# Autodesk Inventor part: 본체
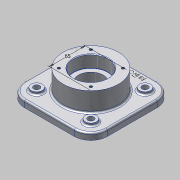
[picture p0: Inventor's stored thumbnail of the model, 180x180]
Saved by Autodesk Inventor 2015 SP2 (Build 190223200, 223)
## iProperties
Created: 2015-07
Part Number: 본체
Material: 알루미늄 6061
Document SubType Name: Modeling
Designer: AMC
Density: 2.7 g/cm^3
Appearance: 알루미늄 - 평지
Author: AMC
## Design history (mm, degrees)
sketch "스케치1"
  geometry: L1 (75, -75)-(-75, -75); L2 (-75, -75)-(-75, 75); L3 (-75, 75)-(75, 75); L4 (75, 75)-(75, -75); L5 (75, -75)-(-75, 75); L6 (-75, -75)-(75, 75); 1 further point
  constraints: 12 end point, 2 midpoint, 2 parallel, 1 horizontal, 1 perpendicular
  dimensions: "d0" = 150 distance of L2.end L3.end; "d1" = 150 distance of L1.end L2.end
extrude "돌출1" new body sketch "스케치1" distance "d2" = 12; taper "d3" = 0 deg
sketch "스케치2"
  geometry: C1 r 50 at (0, 0); 1 further point
  constraints: 1 centre point, 1 coincident
  dimensions: "d4" = 100 diameter of C1
extrude "돌출2" join sketch "스케치2" distance "d5" = 35; taper "d6" = 0 deg
sketch "스케치3"
  geometry: C1 r 50 at (0, 0); 1 further point
  constraints: 1 centre point, 1 coincident
  dimensions: "d7" = 100 diameter of C1
extrude "돌출3" join sketch "스케치3" distance "d8" = 23; taper "d9" = 0 deg
hole "구멍1" diameter "d12" = 45; stored, may be unused: countersink angle "d16" = 90 deg, drill point angle "d18" = 0 deg; dims "d10" = 10, "d11" = 10, "d13" = 6, "d14" = 62, "d15" = 22, "d17" = 8
hole "구멍2" diameter "d21" = 45; stored, may be unused: countersink angle "d25" = 90 deg, drill point angle "d27" = 0 deg; dims "d19" = 10, "d20" = 10, "d22" = 6, "d23" = 62, "d24" = 22, "d26" = 8
fillet "모깎기3" dims "d33" = 30
sketch "스케치8"
  geometry: C1 r 10 at (-49, 49); C2 r 10 at (-49, -49); C3 r 10 at (49, -49); C4 r 10 at (49, 49); 1 further point
  constraints: 4 centre point, 1 horizontal alignment, 9 other
  dimensions: "d34" = 20 diameter of C1; "d37" = 360 deg dimension on point (0, 0) C1.centre (derived); "d39" = 98 distance of C4.centre C1.centre; "d40" = 98 distance of C2.centre C1.centre (derived)
extrude "돌출4" join sketch "스케치8" distance "d41" = 5; taper "d42" = 0 deg
hole "구멍3" diameter "d45" = 11; stored, may be unused: countersink angle "d49" = 90 deg, drill point angle "d51" = 0 deg; dims "d43" = 10, "d44" = 10, "d46" = 6, "d47" = 62, "d48" = 22, "d50" = 8
hole "구멍4" diameter "d54" = 11; stored, may be unused: countersink angle "d58" = 90 deg, drill point angle "d60" = 0 deg; dims "d52" = 10, "d53" = 10, "d55" = 6, "d56" = 62, "d57" = 22, "d59" = 8
hole "구멍5" diameter "d63" = 11; stored, may be unused: countersink angle "d67" = 90 deg, drill point angle "d69" = 0 deg; dims "d61" = 10, "d62" = 10, "d64" = 6, "d65" = 62, "d66" = 22, "d68" = 8
hole "구멍6" diameter "d72" = 11; stored, may be unused: countersink angle "d76" = 90 deg, drill point angle "d78" = 0 deg; dims "d70" = 10, "d71" = 10, "d73" = 6, "d74" = 62, "d75" = 22, "d77" = 8
fillet "모깎기4" dims "d79" = 3
fillet "모깎기5" dims "d80" = 3
fillet "모깎기6" dims "d81" = 0.3
chamfer "모따기1" distance "d82" = 1; stored, may be unused: second distance "d83" = 2, angle "d84" = 45 deg
chamfer "모따기2" distance "d85" = 1; stored, may be unused: second distance "d86" = 2, angle "d87" = 45 deg
sketch "스케치9"
  geometry: L1 (0, 0)-(41, 0); L2 (0, 0)-(28.991, 28.991); A1 r 41 centre (0, 0) between (41, 0) and (28.991, 28.991); 2 further points
  constraints: 4 end point, 2 coincident, 2 point on circle, 1 centre point, 1 horizontal
  dimensions: "d88" = 82 diameter of A1; "d89" = 45 deg angle of L1 L2
hole "구멍7" sketch "스케치9" at (28.991, 28.991) diameter "d90" = 4.917; stored, may be unused: countersink angle "d94" = 90 deg, drill point angle "d96" = 118 deg; dims "d91" = 10, "d92" = 62, "d93" = 22, "d95" = 13
sketch "스케치10"
  geometry: L1 (0, 0)-(41, 0); L2 (0, 0)-(28.991, 28.991); A1 r 41 centre (0, 0) between (41, 0) and (28.991, 28.991); 2 further points
  constraints: 4 end point, 2 coincident, 2 point on circle, 1 centre point, 1 horizontal
  dimensions: "d100" = 82 diameter of A1; "d101" = 45 deg angle of L1 L2
hole "구멍8" sketch "스케치10" at (28.991, 28.991) diameter "d102" = 4.917; stored, may be unused: countersink angle "d106" = 90 deg, drill point angle "d108" = 118 deg; dims "d103" = 10, "d104" = 62, "d105" = 22, "d107" = 13
sketch "스케치11"
  geometry: 2 further points
  constraints: 1 vertical alignment, 1 other
  dimensions: "d115" = 65 distance of point (0, 0) point (0, 65)
node "솔리드1"
pattern_circular "원형 패턴2" dims angle "d110" = 360 deg
pattern_circular "원형 패턴3" dims angle "d113" = 360 deg
